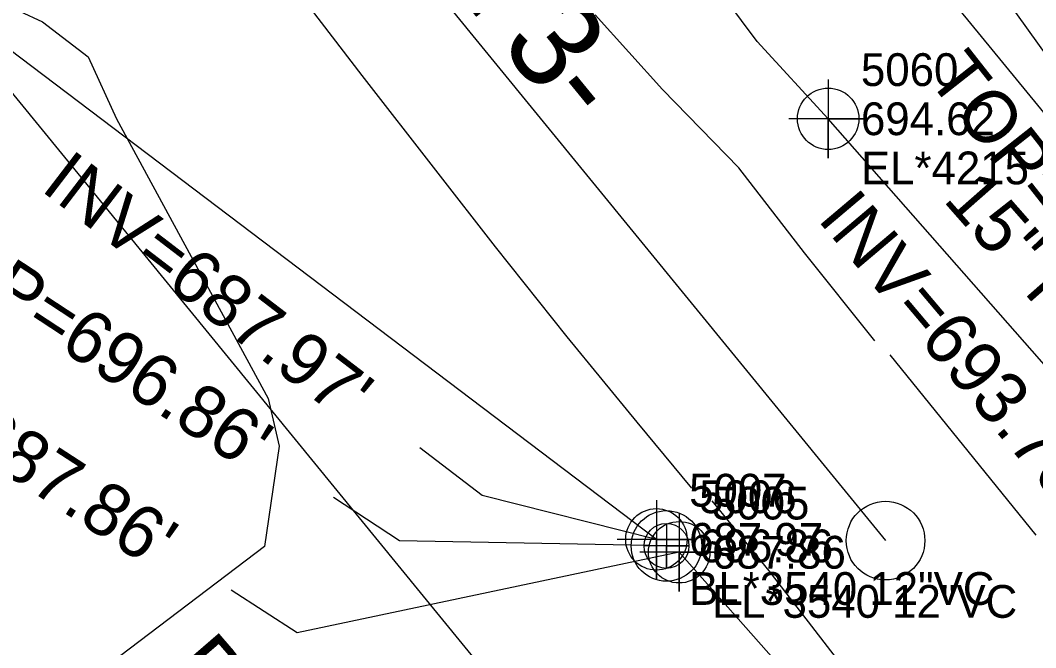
# Model space of a CAD drawing. Extents: x 1516784 to 1522736, y 634838 to 639369.
# Drawn here: x 1520794.2 to 1520871.7, y 637516.5 to 637564.3 of the extents above; entities that cross this region are included whole.
import ezdxf

# ---------------------------------------------------------------- set-up
doc = ezdxf.new("R2010")
doc.units = 0
for name, color, linetype in [('COGO Default Point Number', 7, 'Continuous'), ('CTL Supplemental Horizontal and Vertical Text', 7, 'Continuous'), ('Exist Environmental Wetland Boundary Text', 7, 'Continuous'), ('Exist Horizontal Alignment Direction Label', 7, 'Continuous'), ('Exist Horizontal Alignment Point', 7, 'Continuous'), ('Exist Right of Way Line', 7, 'Continuous'), ('Exist Structure Minor Drop Inlet Top Elevation', 7, 'Continuous'), ('Exist Structure Minor Pipes RCP 15 Inch', 7, 'Continuous'), ('Exist Structure Minor Pipes RCP 15 Inch Cogo Comment', 7, 'Continuous'), ('Exist Structure Minor Pipes RCP 15 Inch Cogo Elevation', 7, 'Continuous'), ('Exist Structure Minor Pipes RCP 15 Inch Cogo Number', 7, 'Continuous'), ('Exist Structure Minor Pipes RCP 15 Inch Cogo Point CELL', 7, 'Continuous'), ('Exist Structure Minor Pipes RCP 15 Inch Invert', 7, 'Continuous'), ('Exist Structure Minor Pipes RCP 15 Inch Leader', 7, 'Continuous'), ('Exist Structure Minor Pipes RCP 15 Inch Text', 7, 'Continuous'), ('Exist Utilities Sanitary Sewer Manhole CELL', 7, 'Continuous'), ('Exist Utilities Sanitary Sewer Manhole Cogo Elevation', 7, 'Continuous'), ('Exist Utilities Sanitary Sewer Manhole Cogo Number', 7, 'Continuous'), ('Exist Utilities Sanitary Sewer Manhole Leader', 7, 'Continuous'), ('Exist Utilities Sanitary Sewer Manhole Text', 7, 'Continuous'), ('Exist Utilities Sanitary Sewer UG Line', 7, 'Continuous'), ('Exist Utilities Sanitary Sewer UG Line Cogo Comment', 7, 'Continuous'), ('Exist Utilities Sanitary Sewer UG Line Cogo Elevation', 7, 'Continuous'), ('Exist Utilities Sanitary Sewer UG Line Cogo Number', 7, 'Continuous'), ('Exist Utilities Sanitary Sewer UG Line Cogo Point CELL', 7, 'Continuous'), ('Exist Utilities Sanitary Sewer UG Line Invert Elevation', 7, 'Continuous'), ('Exist Utilities Sanitary Sewer UG Line Leader', 7, 'Continuous'), ('Exist Vegetation Woods Line', 7, 'Continuous'), ('Scratch_Level_5', 7, 'Continuous')]:
    doc.layers.add(name, color=color, linetype=linetype)

msp = doc.modelspace()

# ---------------------------------------------------------------- linework, layer by layer
at = {"layer": 'COGO Default Point Number'}
for points in [[(1520845.441, 637528.641), (1520841.266, 637533.663), (1520835.94, 637540.173), (1520830.454, 637547.037), (1520825.898, 637552.893), (1520820.298, 637560.11), (1520814.908, 637567.124)], [(1520859.407, 637539.87), (1520854.056, 637546.574), (1520849.033, 637553.063), (1520843.21, 637559.045), (1520838.065, 637564.729)], [(1520860.56, 637538.814), (1520871.704, 637525.037)], [(1520859.069, 637512.34), (1520851.339, 637522.335), (1520847.011, 637527.667)]]:
    msp.add_lwpolyline(points, dxfattribs=at)
at = {"layer": 'Exist Environmental Wetland Boundary Text'}
msp.add_line((1520802.852, 637594.796), (1520860.234, 637524.631), dxfattribs=at)
at = {"layer": 'Exist Horizontal Alignment Point'}
msp.add_circle((1520860.234, 637524.631), 3, dxfattribs=at)
at = {"layer": 'Exist Right of Way Line'}
for p, q in [((1520826.075, 637613.788), (1520951.093, 637460.919)), ((1520779.629, 637575.804), (1520833.334, 637510.135))]:
    msp.add_line(p, q, dxfattribs=at)
at = {"layer": 'Exist Structure Minor Pipes RCP 15 Inch'}
msp.add_line((1520891.108, 637516.714), (1520855.855, 637556.812), dxfattribs=at)
at = {"layer": 'Exist Structure Minor Pipes RCP 15 Inch Cogo Point CELL'}
msp.add_lwpolyline([(1520855.855, 637559.812), (1520855.855, 637553.812), (1520855.855, 637556.812), (1520858.855, 637556.812), (1520852.855, 637556.812)], dxfattribs=at)
msp.add_circle((1520855.855, 637556.812), 2.344, dxfattribs=at)
at = {"layer": 'Exist Structure Minor Pipes RCP 15 Inch Leader'}
msp.add_lwpolyline([(1520855.855, 637556.812), (1520850.431, 637562.719), (1520846.852, 637567.534)], dxfattribs=at)
at = {"layer": 'Exist Utilities Sanitary Sewer Manhole CELL'}
msp.add_lwpolyline([(1520843.511, 637525.94), (1520843.511, 637522.515), (1520843.511, 637524.228), (1520845.224, 637524.228), (1520841.799, 637524.228)], dxfattribs=at)
for radius in [2.694, 1.712]:
    msp.add_circle((1520843.511, 637524.228), radius, dxfattribs=at)
at = {"layer": 'Exist Utilities Sanitary Sewer Manhole Leader'}
msp.add_lwpolyline([(1520843.511, 637524.228), (1520823.124, 637524.621), (1520818.106, 637527.911)], dxfattribs=at)
at = {"layer": 'Exist Utilities Sanitary Sewer UG Line'}
for p, q in [((1520842.743, 637524.73), (1520588.032, 637717.405)), ((1521113.248, 637221.072), (1520844.481, 637523.745))]:
    msp.add_line(p, q, dxfattribs=at)
at = {"layer": 'Exist Utilities Sanitary Sewer UG Line Cogo Point CELL'}
for points in [[(1520842.743, 637527.73), (1520842.743, 637521.73), (1520842.743, 637524.73), (1520845.743, 637524.73), (1520839.743, 637524.73)], [(1520844.481, 637526.745), (1520844.481, 637520.745), (1520844.481, 637523.745), (1520847.481, 637523.745), (1520841.481, 637523.745)]]:
    msp.add_lwpolyline(points, dxfattribs=at)
for centre in [(1520842.743, 637524.73), (1520844.481, 637523.745)]:
    msp.add_circle(centre, 2.344, dxfattribs=at)
at = {"layer": 'Exist Utilities Sanitary Sewer UG Line Leader'}
for points in [[(1520842.743, 637524.73), (1520829.444, 637528.066), (1520824.679, 637531.712)], [(1520844.481, 637523.745), (1520815.325, 637517.602), (1520810.29, 637520.866)]]:
    msp.add_lwpolyline(points, dxfattribs=at)
at = {"layer": 'Exist Vegetation Woods Line'}
for points in [[(1520914.977, 637580.376), (1520909.902, 637577.959), (1520895.881, 637588.648), (1520884.648, 637592.617), (1520889.404, 637574.095), (1520883.698, 637568.875), (1520874.954, 637558.27), (1520860.162, 637578.911), (1520850.896, 637584.64), (1520822.716, 637618.34), (1520793.328, 637652.535), (1520770.306, 637681.215), (1520767.23, 637685.402), (1520765.247, 637689.727), (1520764.122, 637693.769), (1520763.423, 637701.139)], [(1520792.337, 637565.842), (1520795.89, 637564.196), (1520799.375, 637561.527), (1520801.522, 637556.803), (1520813.119, 637535.472), (1520813.952, 637531.849), (1520812.828, 637524.175), (1520799.655, 637514.19), (1520761.261, 637489.106)]]:
    msp.add_lwpolyline(points, dxfattribs=at)

# ---------------------------------------------------------------- texts
at = {"layer": 'CTL Supplemental Horizontal and Vertical Text'}
msp.add_text('BY-14', height=5, rotation=310.80941, dxfattribs=at).set_placement((1520805.198, 637514.718))
at = {"layer": 'Exist Horizontal Alignment Direction Label'}
msp.add_text('-EY3-', height=7, rotation=309.27678, dxfattribs=at).set_placement((1520820.818, 637574.578))
at = {"layer": 'Exist Structure Minor Drop Inlet Top Elevation'}
msp.add_text("TOP=695.93'", height=4, rotation=308.20495, dxfattribs=at).set_placement((1520863.339, 637559.925))
at = {"layer": 'Exist Structure Minor Pipes RCP 15 Inch Cogo Comment'}
msp.add_text('EL*4215', height=2.5, dxfattribs=at).set_placement((1520858.355, 637551.812))
at = {"layer": 'Exist Structure Minor Pipes RCP 15 Inch Cogo Elevation'}
msp.add_text('694.62', height=2.5, dxfattribs=at).set_placement((1520858.355, 637555.562))
at = {"layer": 'Exist Structure Minor Pipes RCP 15 Inch Cogo Number'}
msp.add_text('5060', height=2.5, dxfattribs=at).set_placement((1520858.355, 637559.312))
at = {"layer": 'Exist Structure Minor Pipes RCP 15 Inch Invert'}
msp.add_text("INV=693.70'", height=4, rotation=310.18094, dxfattribs=at).set_placement((1520854.964, 637549.147))
at = {"layer": 'Exist Structure Minor Pipes RCP 15 Inch Text'}
msp.add_text('15" RCP', height=4, rotation=311.321, dxfattribs=at).set_placement((1520864.561, 637550.592))
at = {"layer": 'Exist Utilities Sanitary Sewer Manhole Cogo Elevation'}
msp.add_text('696.86', height=2.5, dxfattribs=at).set_placement((1520846.011, 637522.978))
at = {"layer": 'Exist Utilities Sanitary Sewer Manhole Cogo Number'}
msp.add_text('5006', height=2.5, dxfattribs=at).set_placement((1520846.011, 637526.728))
at = {"layer": 'Exist Utilities Sanitary Sewer Manhole Text'}
msp.add_text("TOP=696.86'", height=4, rotation=326.74711, dxfattribs=at).set_placement((1520785.258, 637547.058))
at = {"layer": 'Exist Utilities Sanitary Sewer UG Line Cogo Comment'}
for s, p in [('BL*3540 12"VC', (1520845.243, 637519.73)), ('EL*3540 12"VC', (1520846.981, 637518.745))]:
    msp.add_text(s, height=2.5, dxfattribs=at).set_placement(p)
at = {"layer": 'Exist Utilities Sanitary Sewer UG Line Cogo Elevation'}
for s, p in [('687.97', (1520845.243, 637523.48)), ('687.86', (1520846.981, 637522.495))]:
    msp.add_text(s, height=2.5, dxfattribs=at).set_placement(p)
at = {"layer": 'Exist Utilities Sanitary Sewer UG Line Cogo Number'}
for s, p in [('5007', (1520845.243, 637527.23)), ('5005', (1520846.981, 637526.245))]:
    msp.add_text(s, height=2.5, dxfattribs=at).set_placement(p)
at = {"layer": 'Exist Utilities Sanitary Sewer UG Line Invert Elevation'}
for s, rotation, p in [("INV=687.97'", 322.57901, (1520795.661, 637551.396)), ("INV=687.86'", 327.04947, (1520779.667, 637538.331))]:
    msp.add_text(s, height=4, rotation=rotation, dxfattribs=at).set_placement(p)
at = {"layer": 'Scratch_Level_5'}
msp.add_text('COLUMN LOCATION', height=500, rotation=335.03733, dxfattribs=at).set_placement((1516680.966, 637558.941))

doc.saveas('drawing.dxf')
